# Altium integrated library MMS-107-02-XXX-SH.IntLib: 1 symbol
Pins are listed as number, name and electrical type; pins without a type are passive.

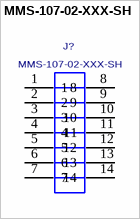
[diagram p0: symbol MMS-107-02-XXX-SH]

## MMS-107-02-XXX-SH
designator J?
2MM SURFACE MOUNT BOX CONNECTOR STRIP ASM.; MANUFACTURER: SAMTEC
footprint MMS-107-02-XXX-SH
pins: 1, 2, 3, 4, 5, 6, 7, 8, 9, 10, 11, 12, 13, 14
